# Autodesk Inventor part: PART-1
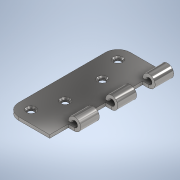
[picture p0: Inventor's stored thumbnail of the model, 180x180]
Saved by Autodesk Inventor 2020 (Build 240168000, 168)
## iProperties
Created: 2023-04
Part Number: PART-1
Material: Generic
Document SubType Name: Sheet Metal
Designer: gzb
Density: 1 g/cm^3
Sheet Metal Rule: Default_mm
Appearance: Steel - Polished
Author: gzb
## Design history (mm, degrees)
node "Face1"
  sketch "Sketch1" dims "d37" = 10
    geometry: L1 (17.5, 45)-(-17.5, 45); L2 (-17.5, 45)-(-17.5, -45); L3 (-17.5, -45)-(17.5, -45); L4 (17.5, -45)-(17.5, 45); L5 (17.5, 45)-(-17.5, -45); L6 (-17.5, 45)-(17.5, -45); L7 (-17.5, -45)-(-27.5, -45); L8 (-27.5, -45)-(-27.5, -30); L9 (-27.5, -30)-(-17.5, -30); L10 (-17.5, -30)-(-17.5, -45); L11 (-17.5, -15)-(-27.5, -15); L12 (-27.5, -15)-(-27.5, 0); L13 (-27.5, 0)-(-17.5, 0); L14 (-17.5, 0)-(-17.5, -15); L15 (-17.5, 15)-(-27.5, 15); L16 (-27.5, 15)-(-27.5, 30); L17 (-27.5, 30)-(-17.5, 30); L18 (-17.5, 30)-(-17.5, 15); L19 (-17.5, -30)-(-17.5, -15); L20 (-17.5, 0)-(-17.5, 15); L21 (-17.5, 30)-(-17.5, 45); 1 further point
    constraints: 42 end point, 4 parallel, 2 collinear, 2 horizontal, 2 midpoint, 2 perpendicular, 2 vertical, 16 other
    dimensions: "d0" = 90 distance of L3.end L1.start; "d1" = 35 distance of L2.end L3.end; "d30" = 10 distance of L2.end L7.end; "d31" = 15 distance of L7.end L8.end; "d34" = 30 distance of L8.end L12.end
feature "Corner Round1" dims "d39" = 10
feature "Corner Round2" dims "d40" = 10
sketch "Sketch4"
  geometry: L1 (-7.5, 45)-(27.5, 45) reference; L2 (17.5, -45)-(-7.5, -45) reference; L3 (-17.5, -35)-(-17.5, 35) reference; L4 (-17.5, 0)-(0, 0); 4 further points
  constraints: 2 end point, 2 symmetric about line, 1 horizontal, 1 midpoint
  dimensions: "d60" = 10 distance from line of point (-7.5, 35) L1; "d61" = 10 distance from line of point (-7.5, 35) L3; "d62" = 30 distance from line of point (0, 15) L1; "d63" = 17.5 distance from line of point (0, 15) L3
feature "Hem3" dims "d2" = 2.5 (= Thickness), "d50" = 2.5 (= BendReliefWidth), "d51" = 1.25 (= BendReliefDepth), "d52" = 5 (= MinimumRemnant), "d53" = 2.5 (= TransitionRadius), "d54" = 275 deg, "d55" = 2.5 (= BendRadius), "d56" = 2.5 (= d55), "SeamGap" = 0.01
pattern_linear "Rectangular Pattern3" dims "d59" = 30
hole "Hole2" sketch "Sketch4" diameter "d64" = 5; stored, may be unused: countersink angle "d68" = 90 deg, drill point angle "d70" = 118 deg; dims "d65" = 6, "d66" = 7.5, "d67" = 2, "d69" = 2.5 (= Thickness)
body "Solid1"
face "Plate1" dims "d2" = 2.5 (= Thickness)
sketch "Sketch5"
  geometry: L1 (0, -2.5)-(0, 0); L2 (-2.49, 2.282)-(-4.981, 2.064); A1 r 2.5 centre (0, 2.5) between (0, 0) and (-2.49, 2.282); A2 r 5 centre (0, 2.5) between (0, -2.5) and (-4.981, 2.064)
  constraints: 4 end point, 4 point on circle
other parameters: "Thickness" = 2.5 (derived), "BendRadius" = 2.5 (= Thickness), "BendReliefWidth" = 2.5 (= Thickness), "BendReliefDepth" = 1.25 (= 0.5 x Thickness), "MinimumRemnant" = 5 (= 2 x Thickness), "TransitionRadius" = 2.5 (= BendRadius), "JacobiRadiusSize" = 2.5 (= BendRadius), "GapSize" = 2.5 (= Thickness)
